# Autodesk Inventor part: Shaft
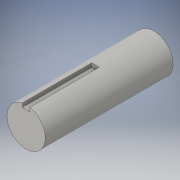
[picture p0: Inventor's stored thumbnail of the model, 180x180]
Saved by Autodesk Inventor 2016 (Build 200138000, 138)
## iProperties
Created: 2020-03
Part Number: Shaft
Material: Generic
Document SubType Name: Modeling
Designer: Furqan
Density: 1 g/cm^3
Appearance: Default
Author: Furqan
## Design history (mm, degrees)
sketch "Sketch1"
  geometry: C1 r 15.24 at (0, 0); 1 further point
  constraints: 1 centre point, 1 coincident
  dimensions: "d0" = 30.48 diameter of C1
extrude "Extrusion1" new body sketch "Sketch1" distance "d1" = 101.6; taper "d2" = 0 deg
sketch "Sketch2"
  geometry: L1 (-2.997, 11.945)-(2.997, 11.945); L2 (2.997, 11.945)-(2.997, 14.942); L3 (-2.997, 11.945)-(-2.997, 14.942); A1 r 15.24 centre (0, 0) between (2.997, 14.942) and (-2.997, 14.942) reference; 1 further point
  constraints: 6 end point, 2 point on circle, 1 horizontal, 1 parallel, 1 perpendicular, 1 vertical
  dimensions: "d3" = 5.9944 distance of L1.start L1.end; "d4" = 2.9972 distance of L1.start L3.end
extrude "Extrusion2" cut sketch "Sketch2" distance "d5" = 54.991; taper "d6" = 0 deg
body "Solid1"
